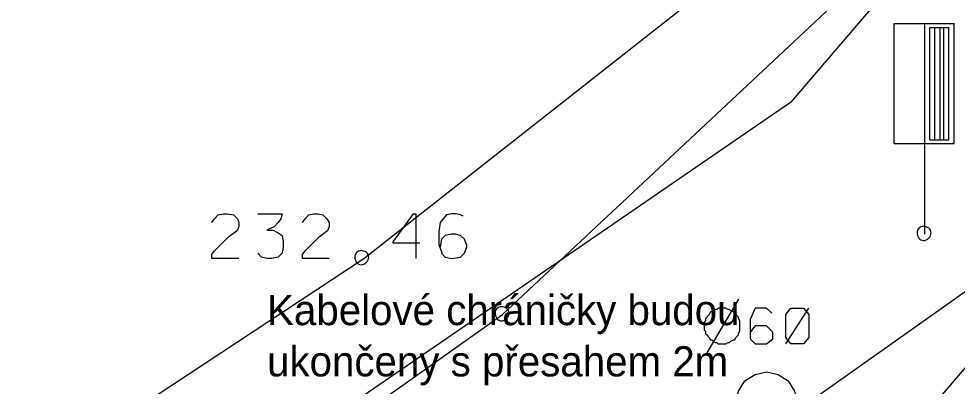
# Model space of a CAD drawing. Extents: x -603337.1 to -603289.6, y -1172912.5 to -1172843.3.
# Drawn here: x -603327.54 to -603311.96, y -1172864.56 to -1172858.46 of the extents above; entities that cross this region are included whole.
import ezdxf

# ---------------------------------------------------------------- set-up
doc = ezdxf.new("R2010")
doc.units = 0
for name, color, linetype in [('GEODET', 7, 'Continuous'), ('Hranice parcel', 7, 'Continuous'), ('Popis prvku', 7, 'Continuous'), ('Vnitřní kresba', 7, 'Continuous')]:
    doc.layers.add(name, color=color, linetype=linetype)

msp = doc.modelspace()

# ---------------------------------------------------------------- linework, layer by layer
at = {"layer": 'GEODET'}
for p, q in [((-603319.506, -1172863.365), (-603310.15, -1172854.602)), ((-603313.008, -1172860.529), (-603313.008, -1172858.539)), ((-603313.008, -1172858.539), (-603312.5, -1172858.539)), ((-603312.5, -1172860.529), (-603312.5, -1172858.539)), ((-603312.5, -1172858.539), (-603312.013, -1172858.539)), ((-603312.415, -1172860.465), (-603312.415, -1172858.603)), ((-603312.415, -1172858.603), (-603312.098, -1172858.603)), ((-603312.331, -1172860.465), (-603312.331, -1172858.603)), ((-603312.246, -1172860.465), (-603312.246, -1172858.603)), ((-603312.182, -1172860.465), (-603312.182, -1172858.603)), ((-603312.098, -1172860.465), (-603312.098, -1172858.603)), ((-603312.013, -1172860.529), (-603312.013, -1172858.539)), ((-603315.125, -1172865.312), (-603308.182, -1172860.402)), ((-603312.415, -1172860.465), (-603312.098, -1172860.465)), ((-603313.008, -1172860.529), (-603312.5, -1172860.529)), ((-603312.5, -1172862.032), (-603312.5, -1172860.529)), ((-603312.5, -1172860.529), (-603312.013, -1172860.529)), ((-603323.57, -1172861.693), (-603323.168, -1172861.693)), ((-603321.326, -1172862.159), (-603320.988, -1172861.693)), ((-603320.988, -1172861.693), (-603320.945, -1172861.693)), ((-603320.945, -1172861.693), (-603320.945, -1172862.434)), ((-603324.057, -1172862.074), (-603323.909, -1172861.968)), ((-603322.554, -1172862.074), (-603322.406, -1172861.968)), ((-603324.29, -1172862.307), (-603324.057, -1172862.074)), ((-603322.787, -1172862.307), (-603322.554, -1172862.074)), ((-603321.326, -1172862.18), (-603321.326, -1172862.159)), ((-603320.882, -1172862.18), (-603321.326, -1172862.18)), ((-603324.332, -1172862.37), (-603324.29, -1172862.307)), ((-603322.829, -1172862.37), (-603322.787, -1172862.307)), ((-603324.332, -1172862.434), (-603324.332, -1172862.37)), ((-603323.888, -1172862.434), (-603324.332, -1172862.434)), ((-603322.829, -1172862.434), (-603322.829, -1172862.37)), ((-603322.385, -1172862.434), (-603322.829, -1172862.434)), ((-603315.59, -1172863.111), (-603316.119, -1172864)), ((-603314.807, -1172863.852), (-603314.426, -1172863.259)), ((-603337.132, -1172875.816), (-603319.506, -1172863.365))]:
    msp.add_line(p, q, dxfattribs=at)
for points in [[(-603337.132, -1172872.534), (-603321.813, -1172862.434), (-603311.145, -1172854.052)], [(-603324.332, -1172861.841), (-603324.29, -1172861.778), (-603324.226, -1172861.714), (-603324.142, -1172861.693), (-603324.078, -1172861.693), (-603323.972, -1172861.714)], [(-603323.972, -1172861.714), (-603323.909, -1172861.778), (-603323.888, -1172861.841), (-603323.888, -1172861.904), (-603323.909, -1172861.968)], [(-603323.168, -1172861.693), (-603323.189, -1172861.778), (-603323.231, -1172861.841), (-603323.295, -1172861.904), (-603323.422, -1172861.968)], [(-603322.829, -1172861.841), (-603322.787, -1172861.778), (-603322.723, -1172861.714), (-603322.639, -1172861.693), (-603322.575, -1172861.693), (-603322.491, -1172861.714)], [(-603322.491, -1172861.714), (-603322.427, -1172861.778), (-603322.385, -1172861.841), (-603322.385, -1172861.904), (-603322.406, -1172861.968)], [(-603320.162, -1172861.735), (-603320.204, -1172861.714), (-603320.289, -1172861.693), (-603320.353, -1172861.693), (-603320.437, -1172861.714), (-603320.543, -1172861.841)], [(-603320.543, -1172861.841), (-603320.564, -1172861.989), (-603320.564, -1172862.201), (-603320.522, -1172862.328)], [(-603323.422, -1172861.968), (-603323.316, -1172861.968), (-603323.231, -1172862.01), (-603323.168, -1172862.053), (-603323.147, -1172862.159), (-603323.147, -1172862.243), (-603323.168, -1172862.349), (-603323.231, -1172862.413), (-603323.337, -1172862.434), (-603323.422, -1172862.434), (-603323.507, -1172862.413), (-603323.57, -1172862.349)], [(-603320.522, -1172862.328), (-603320.522, -1172862.349), (-603320.459, -1172862.413), (-603320.353, -1172862.434), (-603320.204, -1172862.413), (-603320.141, -1172862.349), (-603320.099, -1172862.243), (-603320.099, -1172862.222), (-603320.141, -1172862.116), (-603320.204, -1172862.053), (-603320.289, -1172862.032), (-603320.353, -1172862.032), (-603320.459, -1172862.053), (-603320.522, -1172862.116), (-603320.543, -1172862.243)], [(-603315.04, -1172863.344), (-603315.125, -1172863.259), (-603315.315, -1172863.259), (-603315.4, -1172863.45), (-603315.4, -1172863.767), (-603315.315, -1172863.852), (-603315.125, -1172863.852), (-603315.019, -1172863.767), (-603315.019, -1172863.661), (-603315.125, -1172863.556), (-603315.315, -1172863.556), (-603315.4, -1172863.661)], [(-603315.633, -1172864.826), (-603315.59, -1172864.635), (-603315.484, -1172864.466), (-603315.315, -1172864.36), (-603315.125, -1172864.318), (-603314.934, -1172864.36), (-603314.765, -1172864.466), (-603314.659, -1172864.635), (-603314.617, -1172864.826)]]:
    msp.add_lwpolyline(points, dxfattribs=at)
for points in [[(-603315.865, -1172863.259), (-603315.929, -1172863.259), (-603315.95, -1172863.28), (-603315.971, -1172863.28), (-603316.014, -1172863.302), (-603316.035, -1172863.323), (-603316.056, -1172863.323), (-603316.077, -1172863.365), (-603316.098, -1172863.386), (-603316.119, -1172863.407), (-603316.14, -1172863.429), (-603316.14, -1172863.471), (-603316.162, -1172863.492), (-603316.162, -1172863.534), (-603316.162, -1172863.556), (-603316.162, -1172863.577), (-603316.162, -1172863.619), (-603316.14, -1172863.64), (-603316.14, -1172863.683), (-603316.119, -1172863.704), (-603316.098, -1172863.725), (-603316.077, -1172863.746), (-603316.056, -1172863.788), (-603316.035, -1172863.788), (-603316.014, -1172863.809), (-603315.971, -1172863.831), (-603315.95, -1172863.831), (-603315.929, -1172863.852), (-603315.887, -1172863.852), (-603315.865, -1172863.852), (-603315.823, -1172863.852), (-603315.802, -1172863.852), (-603315.76, -1172863.831), (-603315.738, -1172863.831), (-603315.717, -1172863.809), (-603315.675, -1172863.788), (-603315.654, -1172863.788), (-603315.633, -1172863.746), (-603315.611, -1172863.725), (-603315.59, -1172863.704), (-603315.59, -1172863.683), (-603315.569, -1172863.64), (-603315.569, -1172863.619), (-603315.569, -1172863.577), (-603315.569, -1172863.556), (-603315.569, -1172863.534), (-603315.569, -1172863.492), (-603315.569, -1172863.471), (-603315.59, -1172863.429), (-603315.59, -1172863.407), (-603315.611, -1172863.386), (-603315.633, -1172863.365), (-603315.654, -1172863.323), (-603315.675, -1172863.323), (-603315.717, -1172863.302), (-603315.738, -1172863.28), (-603315.76, -1172863.28), (-603315.802, -1172863.259), (-603315.823, -1172863.259)], [(-603314.722, -1172863.259), (-603314.511, -1172863.259), (-603314.426, -1172863.365), (-603314.426, -1172863.746), (-603314.511, -1172863.852), (-603314.722, -1172863.852), (-603314.807, -1172863.746), (-603314.807, -1172863.365)]]:
    msp.add_lwpolyline(points, close=True, dxfattribs=at)
for centre, radius, start, end in [((-603312.506, -1172862.009), 0.12, 159.5232, 180.5607), ((-603312.485, -1172862.012), 0.142, 179.4975, 217.3724), ((-603312.53, -1172862.001), 0.0957, 135.2549, 159.2174), ((-603312.53, -1172862.002), 0.0957, 110.7826, 134.7451), ((-603312.522, -1172862.025), 0.12, 89.4393, 110.4768), ((-603312.52, -1172862.046), 0.142, 52.6276, 90.5025), ((-603312.492, -1172862.013), 0.0983, 1.2874, 53.4124), ((-603312.505, -1172862.009), 0.111, 334.319, 359.3359), ((-603312.519, -1172862.039), 0.0983, 216.5876, 268.7126), ((-603312.522, -1172862.027), 0.111, 270.6641, 295.681), ((-603312.536, -1172861.997), 0.144, 295.2809, 315.264), ((-603312.535, -1172861.996), 0.144, 314.736, 334.7191), ((-603321.864, -1172862.403), 0.0957, 135.2549, 159.2174), ((-603321.865, -1172862.404), 0.0957, 110.7826, 134.7451), ((-603321.857, -1172862.427), 0.12, 89.4393, 110.4768), ((-603321.854, -1172862.448), 0.142, 52.6276, 90.5025), ((-603321.827, -1172862.415), 0.0983, 1.2874, 53.4124), ((-603321.841, -1172862.411), 0.12, 159.5232, 180.5607), ((-603321.82, -1172862.414), 0.142, 179.4975, 217.3724), ((-603321.853, -1172862.441), 0.0983, 216.5876, 268.7126), ((-603321.87, -1172862.399), 0.144, 295.2809, 315.264), ((-603321.869, -1172862.398), 0.144, 314.736, 334.7191), ((-603321.839, -1172862.411), 0.111, 334.319, 359.3359), ((-603321.857, -1172862.429), 0.111, 270.6641, 295.681), ((-603319.536, -1172863.334), 0.0957, 135.2549, 159.2174), ((-603319.537, -1172863.335), 0.0957, 110.7826, 134.7451), ((-603319.528, -1172863.358), 0.12, 89.4393, 110.4768), ((-603319.526, -1172863.38), 0.142, 52.6276, 90.5025), ((-603319.498, -1172863.346), 0.0983, 1.2874, 53.4124), ((-603319.513, -1172863.343), 0.12, 159.5232, 180.5607), ((-603319.491, -1172863.345), 0.142, 179.4975, 217.3724), ((-603319.525, -1172863.373), 0.0983, 216.5876, 268.7126), ((-603319.542, -1172863.33), 0.144, 295.2809, 315.264), ((-603319.541, -1172863.329), 0.144, 314.736, 334.7191), ((-603319.511, -1172863.343), 0.111, 334.319, 359.3359), ((-603319.528, -1172863.36), 0.111, 270.6641, 295.681)]:
    msp.add_arc(centre, radius, start, end, dxfattribs=at)
at = {"layer": 'Hranice parcel'}
msp.add_lwpolyline([(-603298.952, -1172843.252), (-603299.09, -1172844.28), (-603304.96, -1172857.09), (-603308.55, -1172860.43), (-603313.77, -1172866.51), (-603337.132, -1172880.511)], dxfattribs=at)
at = {"layer": 'Vnitřní kresba'}
for p, q in [((-603307.99, -1172851.99), (-603314.73, -1172859.85)), ((-603314.73, -1172859.85), (-603337.132, -1172875.214))]:
    msp.add_line(p, q, dxfattribs=at)

# ---------------------------------------------------------------- texts
at = {"layer": 'Popis prvku'}
for s, p in [('Kabelové chráničky budou', (-603323.417, -1172863.542)), ('ukončeny s přesahem 2m', (-603323.417, -1172864.392))]:
    msp.add_text(s, height=0.5, dxfattribs=at).set_placement(p)

doc.saveas('drawing.dxf')
